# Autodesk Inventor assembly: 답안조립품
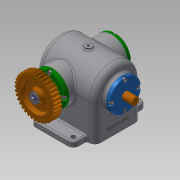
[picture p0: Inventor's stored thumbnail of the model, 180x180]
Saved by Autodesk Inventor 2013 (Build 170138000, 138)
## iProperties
Created: 2019-05
Part Number: 답안조립품
Document SubType Name: Assembly
Designer: Administrator
Author: Administrator
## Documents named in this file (16)
- C:\Users\Administrator\Desktop\390504V1032\답안조립품.iam
- C:\Users\Administrator\Desktop\390504V1032\본체.ipt
- C:\Users\Administrator\Desktop\390504V1032\가변스프링.ipt
- C:\Users\Administrator\Desktop\390504V1032\가이드부시.ipt
- C:\Users\Administrator\Desktop\390504V1032\베어링 6203.ipt
- C:\Users\Administrator\Desktop\390504V1032\볼트 M4x8.ipt
- C:\Users\Administrator\Desktop\390504V1032\볼트 M4x10.ipt
- C:\Users\Administrator\Desktop\390504V1032\스퍼기어.ipt
- C:\Users\Administrator\Desktop\390504V1032\스프링와셔.ipt
- C:\Users\Administrator\Desktop\390504V1032\슬라이더.ipt
- C:\Users\Administrator\Desktop\390504V1032\오일 실 17 32 8.ipt
- C:\Users\Administrator\Desktop\390504V1032\커버 A.ipt
- C:\Users\Administrator\Desktop\390504V1032\커버 B.ipt
- C:\Users\Administrator\Desktop\390504V1032\키 4x4x14.ipt
- C:\Users\Administrator\Desktop\390504V1032\편심축.ipt
- C:\Users\Administrator\Desktop\390504V1032\평와셔.ipt
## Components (2 placed, 2 different names)
1. 가변스프링:1
2. 가이드부시:1
